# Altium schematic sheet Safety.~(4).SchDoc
size A
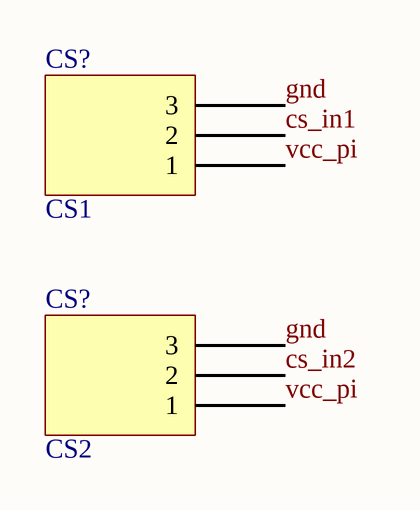
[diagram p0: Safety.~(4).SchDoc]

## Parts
(Parts that share a designator on the sheet are numbered #1, #2 ... from top to bottom, then left to right.)
CS?#1  CS1  [ACS712]
CS?#2  CS2  [ACS712]

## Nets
cs_in1: CS?#1.2
cs_in2: CS?#2.2
gnd: CS?#1.3 CS?#2.3
vcc_pi: CS?#1.1 CS?#2.1

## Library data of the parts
CS?#1 CS?#2 = ACS712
